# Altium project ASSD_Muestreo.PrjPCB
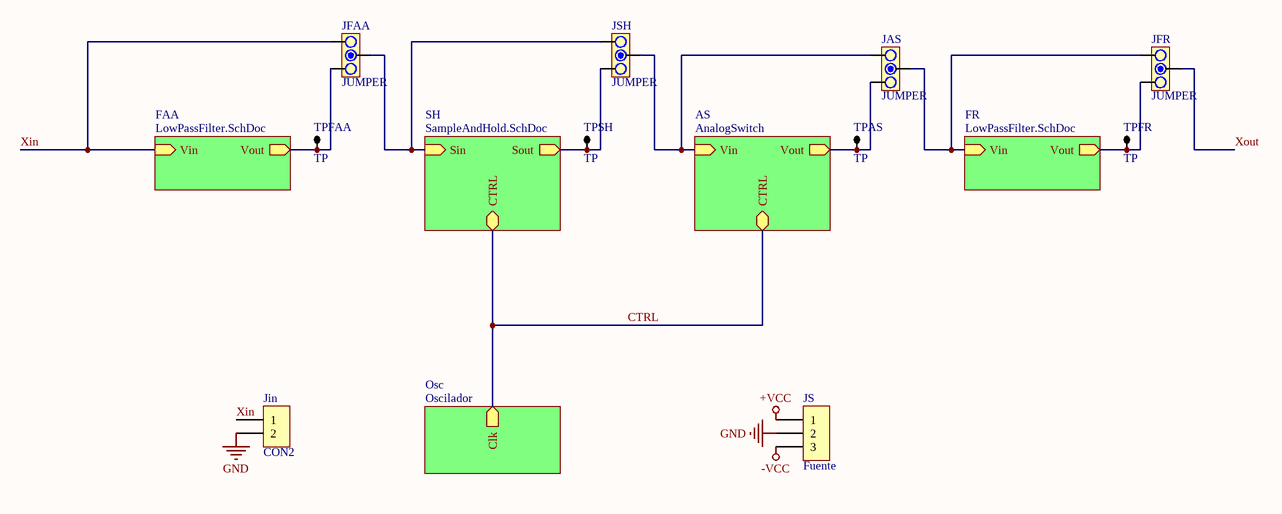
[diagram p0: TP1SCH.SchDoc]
4 sheets, 71 parts. Net scope: hierarchical (ports join the sheet entries above them; power ports are global).
Board file: TP1PCB.PcbDoc
Sheets:
  TP1SCH.SchDoc
    FAA = LowPassFilter.SchDoc
    SH = SampleAndHold.SchDoc
    FR = LowPassFilter.SchDoc
    Osc = Oscilador.SchDoc

## Sheet TP1SCH.SchDoc
size A4

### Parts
JAS  JUMPER  [JUMPER3]
JFAA  JUMPER  [JUMPER3]
JFR  JUMPER  [JUMPER3]
Jin  CON2  [SIP2]
JS  Fuente  [SIP3]
JSH  JUMPER  [JUMPER3]
TPAS  TP  [TPTH]
TPFAA  TP  [TPTH]
TPFR  TP  [TPTH]
TPSH  TP  [TPTH]

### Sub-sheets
AS = AnalogSwitch (file not in this document): Vin (in), CTRL (bidir), Vout (out)
FAA = LowPassFilter.SchDoc: Vin (in), Vout (out)
FR = LowPassFilter.SchDoc: Vin (in), Vout (out)
Osc = Oscilador: Clk (out)
SH = SampleAndHold.SchDoc: Sin (in), Sout (out), CTRL (bidir)

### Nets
+VCC: JS.1
-VCC: JS.3
GND: Jin.2 JS.2
CTRL: sheet SH/CTRL, sheet AS/CTRL, sheet Osc/Clk
V4out: JFAA.1 TPFAA.1 ; sheet FAA/Vout
V4out: JFR.1 TPFR.1 ; sheet FR/Vout  [a separate net that carries the same name]
Xin: JFAA.3 Jin.1 ; sheet FAA/Vin
Xin: JFAA.2 JSH.3 ; sheet SH/Sin  [a separate net that carries the same name]
Xout: JSH.1 TPSH.1 ; sheet SH/Sout
Xout: JFR.2  [a separate net that carries the same name]
NetJAS_1: JAS.1 TPAS.1 ; sheet AS/Vout
NetJAS_2: JAS.2 JFR.3 ; sheet FR/Vin
NetJAS_3: JAS.3 JSH.2 ; sheet AS/Vin

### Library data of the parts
JAS JFAA JFR JSH = JUMPER3
JS = CON3

## Sheet LowPassFilter.SchDoc
size A4
Used 2 times, as channels FAA, FR. Parts and nets are listed once, with the designators drawn on the sheet.
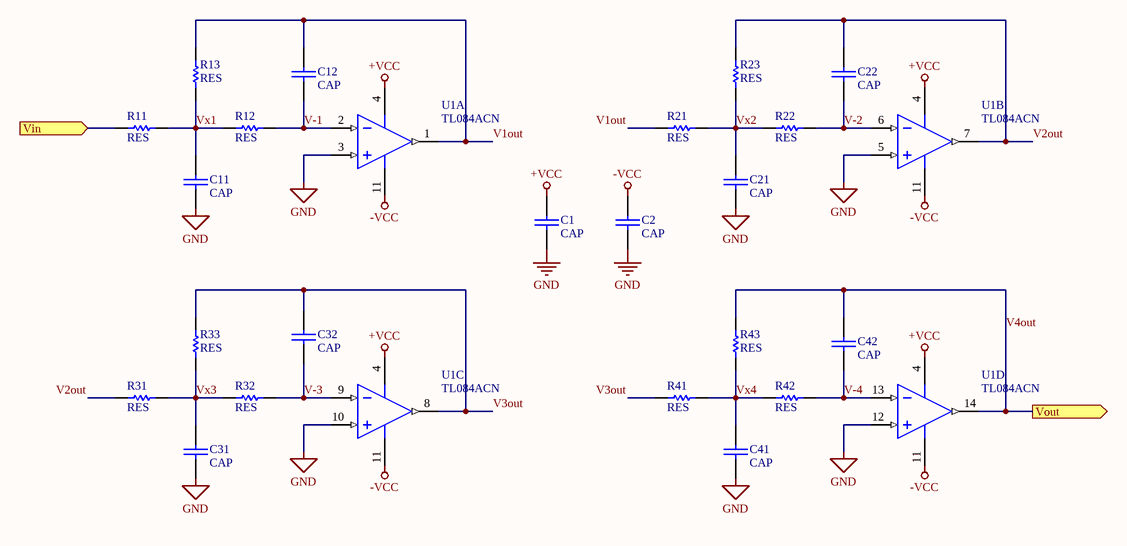
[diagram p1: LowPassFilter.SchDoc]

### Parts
C1  CAP  [CAP200]
C2  CAP  [CAP200]
C11  CAP  [0805]
C12  CAP  [0805]
C21  CAP  [0805]
C22  CAP  [0805]
C31  CAP  [0805]
C32  CAP  [0805]
C41  CAP  [0805]
C42  CAP  [0805]
R11  RES  [0805]
R12  RES  [0805]
R13  RES  [0805]
R21  RES  [0805]
R22  RES  [0805]
R23  RES  [0805]
R31  RES  [0805]
R32  RES  [0805]
R33  RES  [0805]
R41  RES  [0805]
R42  RES  [0805]
R43  RES  [0805]
U1  TL084ACN  [TI-N14]  (parts A,B,C,D of 4)

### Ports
Vin (in), Vout (out)

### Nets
+VCC: C1.1 U1.4(VCC+)
-VCC: C2.1 U1.11(VCC-)
GND: C1.2 C2.2 C11.2 C21.2 C31.2 C41.2 U1.3(IN1+) U1.5(IN2+) U1.10(IN3+) U1.12(IN4+)
V1out: C12.1 R13.1 R21.1 U1.1(OUT1)
V2out: C22.1 R23.1 R31.1 U1.7(OUT2)
V3out: C32.1 R33.1 R41.1 U1.8(OUT3)
V4out: C42.1 R43.1 U1.14(OUT4) ; port Vout
V-1: C12.2 R12.2 U1.2(IN1-)
V-2: C22.2 R22.2 U1.6(IN2-)
V-3: C32.2 R32.2 U1.9(IN3-)
V-4: C42.2 R42.2 U1.13(IN4-)
Vin: R11.1 ; port Vin
Vx1: C11.1 R11.2 R12.1 R13.2
Vx2: C21.1 R21.2 R22.1 R23.2
Vx3: C31.1 R31.2 R32.1 R33.2
Vx4: C41.1 R41.2 R42.1 R43.2

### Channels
FAA: designators end in _FAA; ports Vin=Xin Vout=V4out
FR: designators end in _FR; ports Vin=NetJAS_2 Vout=V4out

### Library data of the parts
U1 = TL084ACN: JFET-Input Operational Amplifier, 7 to 36 V, 0 to 70 degC, 14-pin DIP (N14), Pb-Free (RoHS); Manufacturer: Texas Instruments; CMRR(Min)(dB): 75; GBW(Typ)(MHz): 3; IIB(Max)(pA): 200; Iq per channel(Max)(mA): 2.8; Number of Channels: 4; Offset Drift(Typ)(uV/C): 18; Rating: Catalog; Slew Rate(Typ)(V/us): 13; Sub Family: General Purpose Amplifier, High Supply Voltage Amplifier (>=30V); Total Supply Voltage(Max)(+5V is 5, +/-5V is 10): 36; Total Supply Voltage(Min)(+5V is 5, +/-5V is 10): 7; Vio (25C)(Max)(mV): 6

## Sheet SampleAndHold.SchDoc
size A4
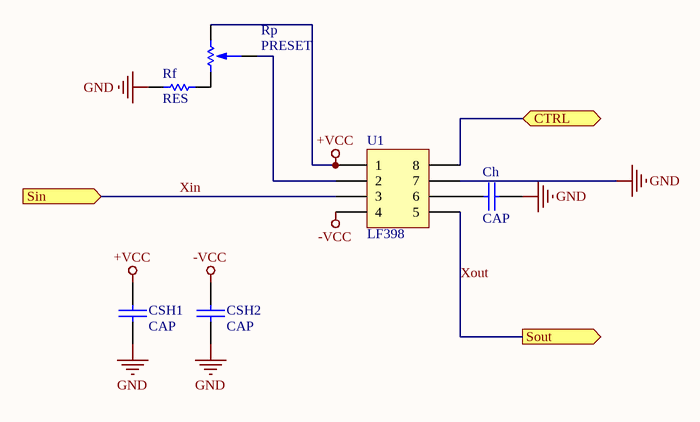
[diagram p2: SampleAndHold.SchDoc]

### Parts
Ch  CAP  [CAP200]
CSH1  CAP  [CAP200]
CSH2  CAP  [CAP200]
Rf  RES  [RES400]
Rp  PRESET  [PRESET V]
U1  LF398  [DIP8]

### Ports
CTRL (bidir), Sin (in), Sout (out)

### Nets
+VCC: CSH1.1 Rp.1 U1.1
-VCC: CSH2.1 U1.4
GND: Ch.2 CSH1.2 CSH2.2 Rf.1 U1.7
CTRL: U1.8 ; port CTRL
Xin: U1.3 ; port Sin
Xout: U1.5 ; port Sout
NetCh_1: Ch.1 U1.6
NetRf_2: Rf.2 Rp.3
NetRp_2: Rp.2 U1.2

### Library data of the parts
U1 = IC_DIP8

## Sheet Oscilador.SchDoc
size A4
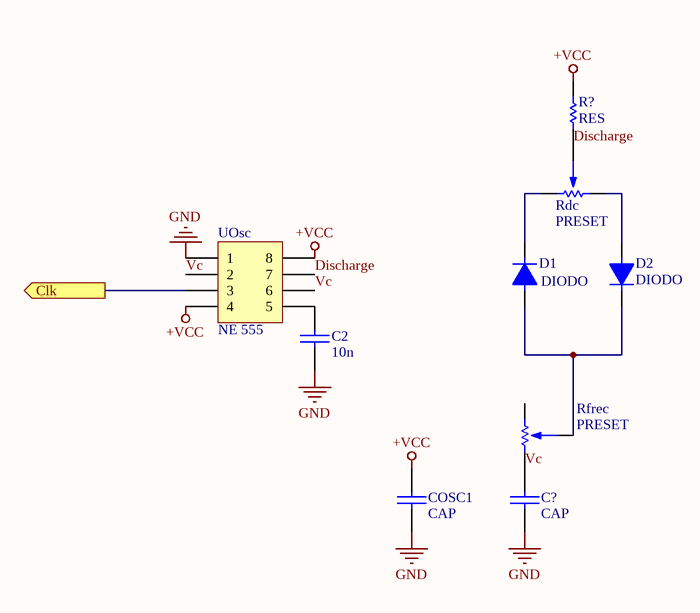
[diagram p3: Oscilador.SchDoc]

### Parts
C2  10n  [CAP200]
C?  CAP  [CAP200]
COSC1  CAP  [CAP200]
D1  DIODO  [DO41]
D2  DIODO  [DO41]
R?  RES  [RES400]
Rdc  PRESET  [PRESET V]
Rfrec  PRESET  [PRESET V]
UOsc  NE 555  [DIP8]

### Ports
Clk (out)

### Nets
+VCC: COSC1.1 R?.1 UOsc.4 UOsc.8
GND: C2.2 C?.2 COSC1.2 UOsc.1
CTRL: UOsc.3 ; port Clk
Discharge: R?.2 Rdc.2 UOsc.7
Vc: C?.1 Rfrec.3 UOsc.2 UOsc.6
NetC2_1: C2.1 UOsc.5
NetD1_1: D1.1 D2.2 Rfrec.2
NetD1_2: D1.2 Rdc.1
NetD2_1: D2.1 Rdc.3

Not connected (* = marked no-connect by the designer): Rfrec 1

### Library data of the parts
C2 = CAP
UOsc = IC_DIP8

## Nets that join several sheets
+VCC: TP1SCH (JS.1), FAA (C1_FAA.1 U1_FAA.4), SampleAndHold (CSH1.1 Rp.1 U1.1), FR (C1_FR.1 U1_FR.4), Oscilador (COSC1.1 R?.1 UOsc.4 UOsc.8)
-VCC: TP1SCH (JS.3), FAA (C2_FAA.1 U1_FAA.11), SampleAndHold (CSH2.1 U1.4), FR (C2_FR.1 U1_FR.11)
GND: TP1SCH (Jin.2 JS.2), FAA (10 pins), SampleAndHold (5 pins), FR (10 pins), Oscilador (C2.2 C?.2 COSC1.2 UOsc.1)
CTRL: SampleAndHold (U1.8), Oscilador (UOsc.3)
NetJAS_2: TP1SCH (JAS.2 JFR.3), FR (R11_FR.1)
V4out: TP1SCH (JFAA.1 TPFAA.1), FAA (C42_FAA.1 R43_FAA.1 U1_FAA.14)
V4out: TP1SCH (JFR.1 TPFR.1), FR (C42_FR.1 R43_FR.1 U1_FR.14)
Xin: TP1SCH (JFAA.3 Jin.1), FAA (R11_FAA.1)
Xin: TP1SCH (JFAA.2 JSH.3), SampleAndHold (U1.3)
Xout: TP1SCH (JSH.1 TPSH.1), SampleAndHold (U1.5)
